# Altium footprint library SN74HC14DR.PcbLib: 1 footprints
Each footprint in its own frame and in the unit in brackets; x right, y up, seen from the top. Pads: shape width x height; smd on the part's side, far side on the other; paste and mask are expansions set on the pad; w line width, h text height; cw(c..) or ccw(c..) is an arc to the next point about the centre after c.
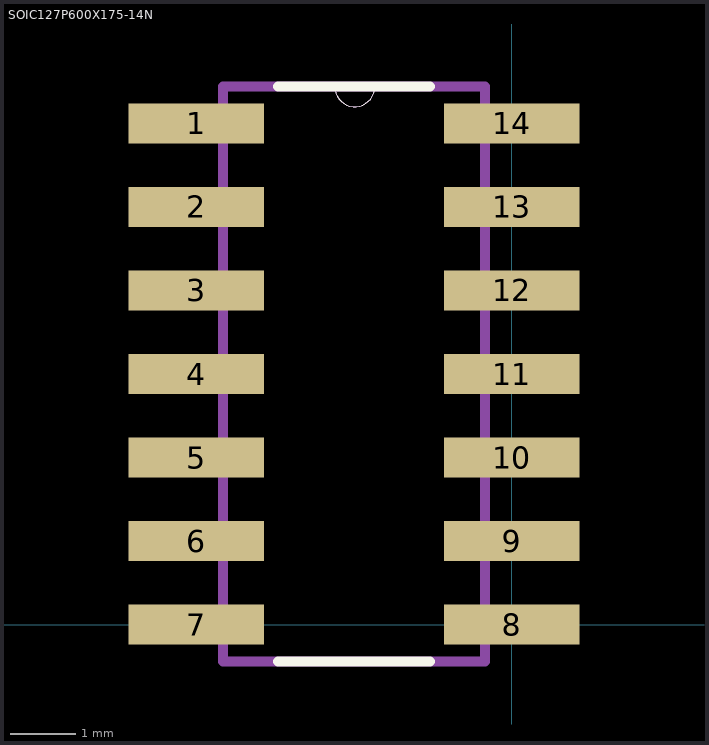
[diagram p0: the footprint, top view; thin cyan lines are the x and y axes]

## SOIC127P600X175-14N [mil]
pads (14):
  rect 81x24 smd: 1(-189,300) 2(-189,250) 3(-189,200) 4(-189,150) 5(-189,100) 6(-189,50) 7(-189,0) 8(0,0) 9(0,50) 10(0,100) 11(0,150) 12(0,200) 13(0,250) 14(0,300)
Top Overlay:
  lines w0: -106,322 ccw(c-94,322) -82,322
  lines w6: -140,-22 -49,-22 ; -140,322 -106,322 -82,322 -49,322
Mechanical 4:
  lines w0: -106,322 ccw(c-94,322) -82,322 cw(c-94,322) -106,322
  lines w6: -173,-22 -173,322 ; -173,-22 -16,-22 ; -173,-22 -173,322 ; -173,-22 -16,-22 ; -173,322 -106,322 ; -173,322 -106,322 ; -106,322 -82,322 ; -106,322 -82,322 ; -82,322 -16,322 ; -82,322 -16,322 ; -16,-22 -16,322 ; -16,-22 -16,322 ; -189,0 -173,0 -189,0 ; -189,50 -173,50 -189,50 ; -189,100 -173,100 -189,100 ; -189,150 -173,150 -189,150 ; -189,200 -173,200 -189,200 ; -189,250 -173,250 -189,250 ; -189,300 -173,300 -189,300 ; -16,0 0,0 -16,0 ; -16,50 0,50 -16,50 ; -16,100 0,100 -16,100 ; -16,150 0,150 -16,150 ; -16,200 0,200 -16,200 ; -16,250 0,250 -16,250 ; -16,300 0,300 -16,300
